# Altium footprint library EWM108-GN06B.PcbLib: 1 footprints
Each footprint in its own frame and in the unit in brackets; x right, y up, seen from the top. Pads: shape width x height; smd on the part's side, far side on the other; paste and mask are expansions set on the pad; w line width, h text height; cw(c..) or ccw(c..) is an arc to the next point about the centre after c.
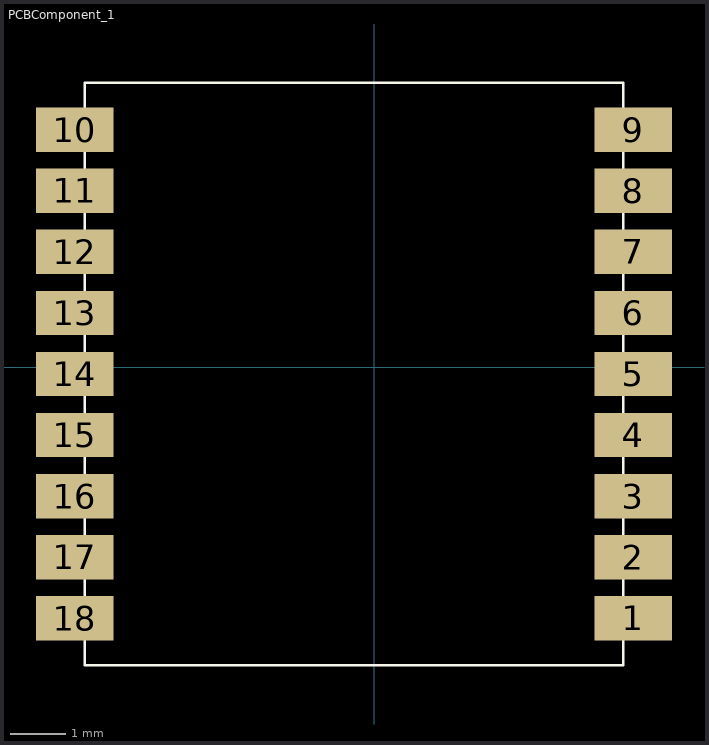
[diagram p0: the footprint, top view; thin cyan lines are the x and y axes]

## PCBComponent_1 [mm]
pads (18):
  rect 1.397x0.8 smd paste+0 mask+0: 1(4.674,-4.519) 2(4.674,-3.419) 3(4.674,-2.319) 4(4.674,-1.219) 5(4.674,-0.119) 6(4.674,0.981) 7(4.674,2.081) 8(4.674,3.181) 9(4.674,4.281) 10(-5.396,4.281) 11(-5.396,3.181) 12(-5.396,2.081) 13(-5.396,0.981) 14(-5.396,-0.119) 15(-5.396,-1.219) 16(-5.396,-2.319) 17(-5.396,-3.419) 18(-5.396,-4.519)
Top Overlay:
  lines w0.05: -5.211,-5.369 4.489,-5.369 4.489,5.131 -5.211,5.131 -5.211,-5.369 ; -5.211,-5.369 -5.211,-5.369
